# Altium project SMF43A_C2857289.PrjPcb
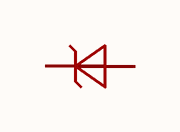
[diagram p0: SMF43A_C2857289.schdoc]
1 sheet, 1 parts. Net scope: global (net labels, ports and power ports of the same name join across sheets).

## Sheet SMF43A_C2857289.schdoc
size 127 x 101 mm

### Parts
D?  smf43a_c2857289  [SOD-123FL_L2.7-W1.8-LS3.7-RD]  (value not drawn)

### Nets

Not connected (* = marked no-connect by the designer): D? 1 2

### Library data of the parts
D? = smf43a_c2857289: 极性:单向;反向截止电压(Vrwm):43V;钳位电压:69.4V;峰值脉冲电流(Ipp):2.9A;峰值脉冲功率(Ppp):200W@10/1000us;击穿电压(VBR):47.8V;; Manufacturer: JSMSEMI(杰盛微); ManufacturerPart: SMF43A; AddInBom: yes; ModelId: 86f9151e155e4fe2af0c4f2e0a80302e; ModelName: SOD-123FL_L2.8-W1.8-H1.1-LS3.6; ModelTransform: 141.732,70.866,0,180,0,0,0,0,0; Polarity: 单向; Reverse Stand-Off Voltage (Vrwm): 43V; Clamping Voltage: 69.4V; Peak Pulse Current (Ipp): 2.9A; Voltage - Breakdown: 47.8V; Reverse Leakage Current (Ir): 1uA; Number of Channels: 单路; Type: TVS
